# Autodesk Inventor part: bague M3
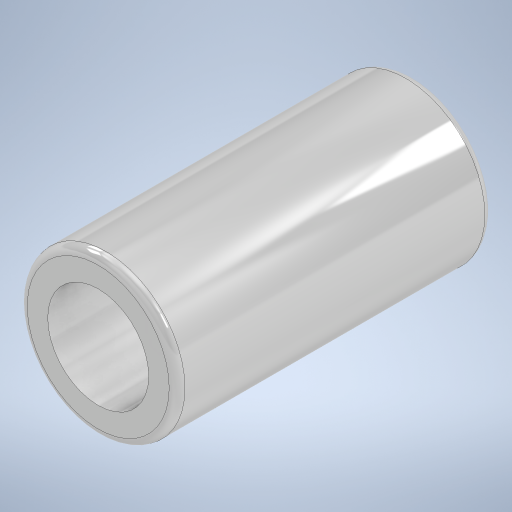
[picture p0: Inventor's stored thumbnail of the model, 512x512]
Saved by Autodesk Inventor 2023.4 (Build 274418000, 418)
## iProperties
Created: 2025-07
Part Number: bague M3
Material: Aluminium 6061
Document SubType Name: Modeling
Designer: mel
Density: 2.7 g/cm^3
Appearance: Aluminum - Poli
Author: mel
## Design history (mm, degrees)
sketch "Esquisse1"
  geometry: C1 r 2.5 at (0, 0); C2 r 1.6 at (0, 0); 1 further point
  constraints: 2 centre point, 2 coincident
  dimensions: "d0" = 5 diameter of C1; "d1" = 3.2 diameter of C2
extrude "Extrusion1" new body sketch "Esquisse1" distance "d2" = 10; taper "d3" = 0 deg
fillet "Congé1" dims "d4" = 0.25
node "Solide1"
